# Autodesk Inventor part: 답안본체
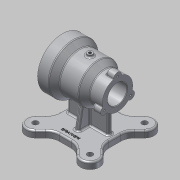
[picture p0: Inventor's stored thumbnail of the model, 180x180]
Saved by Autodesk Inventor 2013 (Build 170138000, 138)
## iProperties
Created: 2017-03
Part Number: 답안본체
Material: 알루미늄 6061
Document SubType Name: Modeling
Designer: Administrator
Density: 2.71 g/cm^3
Mass: 1007.36 g
Surface Area: 842.208 cm^2
Volume: 371.721 cm^3
Author: Administrator
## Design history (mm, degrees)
sketch "스케치2"
  geometry: L1 (0, 0)-(-100, 0); L2 (-100, 18.5)-(-100, 27.5); L3 (-100, 27.5)-(-77, 27.5); L4 (-77, 27.5)-(-65, 36); L5 (-65, 36)-(-31, 36); L6 (-31, 36)-(-20, 45); L7 (-20, 45)-(0, 45); L8 (0, 45)-(0, 36); L9 (-1, 35)-(-20, 35); L10 (-23, 32)-(-23, 29); L11 (-26, 26)-(-67, 26); L12 (-70, 23)-(-70, 20.5); L13 (-73, 17.5)-(-99, 17.5); L14 (-1, 35)-(0, 36); L15 (-99, 17.5)-(-100, 18.5); A1 r 3 centre (-20, 32) between (-20, 35) and (-23, 32); A2 r 3 centre (-26, 29) between (-26, 26) and (-23, 29); A3 r 3 centre (-67, 23) between (-67, 26) and (-70, 23); A4 r 3 centre (-73, 20.5) between (-73, 17.5) and (-70, 20.5); 6 further points
  constraints: 30 end point, 14 point on line, 8 point on circle, 8 tangent, 5 parallel, 5 perpendicular, 4 centre point, 3 equal radius, 1 horizontal
  dimensions: "d0" = 100 distance of L1.start L1.end; "d2" = 90 diameter of L7 L1; "d3" = 20 distance of L6.end L7.end; "d4" = 31 horizontal distance of L5.end L7.end; "d5" = 65 horizontal distance of L4.end L7.end; "d6" = 23 distance of L2.end L3.end; "d7" = 72 diameter of L5 L1; "d8" = 55 diameter of L3 L1; "d9" = 70 diameter of L9 L1; "d10" = 52 diameter of L11 L1; "d11" = 35 diameter of L13 L1; "d12" = 23 distance between parallel lines of L10 L8; "d13" = 47 distance of point (-23, 26) point (-70, 26); "d14" = 3 radius of A1; "d15" = 1 distance of L9.start point (0, 35); "d16" = 1 distance of L8.end point (0, 35) (= d15); "d17" = 1 distance of L13.end point (-100, 17.5) (= d15); "d18" = 1 distance of L2.start point (-100, 17.5) (= d17)
revolve "회전1" sketch "스케치2" stored, may be unused: angle "d19" = 90 deg
node "작업 평면3"
sketch "스케치4"
  geometry: L1 (100, 27.5)-(100, -27.5) reference; L2 (0, 0)-(100, 0); L3 (50, 0)-(50, -68.709); L4 (39.397, 45)-(60.603, 45); L5 (95, 10.603)-(95, -10.603); L6 (60.603, -45)-(39.397, -45); L7 (5, -10.603)-(5, 45); L8 (5, 45)-(95, -45); L9 (95, 45)-(5, -45); L10 (50, 0)-(0.503, 49.497); L11 (50, 0)-(99.497, 49.497); L12 (50, 0)-(0.503, -49.497); L13 (50, 0)-(99.497, -49.497); L14 (12.523, 61.518)-(21.719, 52.322); L15 (-11.518, 37.477)-(5, 20.958); L16 (-11.518, -37.477)-(-2.322, -28.281); L17 (12.523, -61.518)-(21.719, -52.322); L18 (87.477, -61.518)-(78.281, -52.322); L19 (111.518, -37.477)-(102.322, -28.281); L20 (87.477, 61.518)-(78.281, 52.322); L21 (111.518, 37.477)-(102.322, 28.281); A1 r 70 centre (50, 0) between (0.503, 49.497) and (99.497, 49.497); A2 r 17 centre (0.503, 49.497) between (12.523, 61.518) and (-11.518, 37.477); A3 r 17 centre (99.497, -49.497) between (87.477, -61.518) and (111.518, -37.477); A4 r 17 centre (0.503, -49.497) between (-11.518, -37.477) and (12.523, -61.518); A5 r 17 centre (99.497, 49.497) between (87.477, 61.518) and (111.518, 37.477); A6 r 25 centre (39.397, 70) between (21.719, 52.322) and (39.397, 45); A7 r 25 centre (60.603, 70) between (60.603, 45) and (78.281, 52.322); A8 r 25 centre (120, 10.603) between (102.322, 28.281) and (95, 10.603); A9 r 25 centre (120, -10.603) between (95, -10.603) and (102.322, -28.281); A10 r 25 centre (39.397, -70) between (39.397, -45) and (21.719, -52.322); A11 r 25 centre (-20, -10.603) between (-2.322, -28.281) and (5, -10.603); A12 r 25 centre (60.603, -70) between (78.281, -52.322) and (60.603, -45); 1 further point
  constraints: 40 end point, 26 point on circle, 22 tangent, 12 centre point, 12 point on line, 8 equal radius, 7 parallel, 6 midpoint, 5 coincident, 5 perpendicular, 1 collinear, 1 horizontal
  dimensions: "d38" = 140 diameter of A1; "d40" = 90 distance of L7.end L9.start; "d41" = 90 distance of L9.start L8.end; "d42" = 45 deg angle of L2 L10; "d43" = 90 deg angle of L11 L8; "d44" = 90 deg angle of L12 L13; "d45" = 34 diameter of A2; "d46" = 25 radius of A6; "d95" = 25 radius of A12
extrude "돌출2" join sketch "스케치4" distance "d47" = 12; taper "d48" = 0 deg
sketch "스케치5"
  geometry: L1 (39.397, -45)-(60.603, -45) reference; L2 (60.603, 45)-(39.397, 45) reference; L3 (50, 45)-(50, -45); L4 (50, 0)-(13, 0); L5 (13, 0)-(50, 0); L6 (87, 0)-(50, 0); L7 (87, 0)-(87, 4); L8 (87, 4)-(13, 4); L9 (13, 4)-(13, -4); L10 (13, -4)-(87, -4); L11 (87, -4)-(87, 0); 2 further points
  constraints: 18 end point, 4 collinear, 4 perpendicular, 3 midpoint, 2 parallel
  dimensions: "d52" = 4 distance between parallel lines of L8 L4; "d53" = 8 distance of L8.end L9.end; "d54" = 37 horizontal distance of L4.start L9.end; "d55" = 37 distance of L6.start L4.start
extrude "돌출3" join sketch "스케치5" stored distance "d56" = 12; taper "d57" = 0 deg
node "작업 평면4"
sketch "스케치6"
  geometry: L1 (-28.281, -70)-(-10.603, -70) reference; L2 (-28.281, -70)-(-37.477, -70) reference; L3 (-37.477, -70)-(-66.497, -70) reference; L4 (37.477, -70)-(20.958, -70) reference; L5 (66.497, -70)-(37.477, -70) reference; L6 (18.14, -31.096)-(25, -70); A1 r 36 centre (0, 0) between (4, -35.777) and (-4, -35.777) reference; 3 further points
  constraints: 2 end point, 1 point on circle, 1 point on line
  dimensions: "d62" = 100 deg angle of L5 L6; "d63" = 25 horizontal distance of L6.end point (0, 0)
feature "리브1" sketch "스케치6" dims "d64" = 1, "d65" = 8, "d66" = 0, "d67" = 0, "d68" = 1, "d69" = 1
sketch "스케치7"
  geometry: L1 (-28.281, -70)-(-10.603, -70) reference; L2 (-37.477, -70)-(-66.497, -70) reference; L3 (-28.281, -70)-(-37.477, -70) reference; L4 (-18.14, -31.096)-(-25, -70); A1 r 36 centre (0, 0) between (4, -35.777) and (-4, -35.777) reference; 2 further points
  constraints: 2 end point, 1 point on circle, 1 point on line
  dimensions: "d70" = 25 horizontal distance of point (0, 0) L4.end; "d71" = 100 deg angle of L2 L4
feature "리브2" sketch "스케치7" dims "d72" = 1, "d73" = 8, "d74" = 0, "d75" = 0, "d76" = 1, "d77" = 1
sketch "스케치8"
  geometry: L1 (-27.5, 0)-(0, 0); L2 (0, 0)-(13.75, -23.816); L3 (0, 0)-(13.75, 23.816); C1 r 20.5 at (0, 0) reference; C2 r 7 at (-27.5, 0); C3 r 26 at (0, 0) reference; A1 r 27.5 centre (0, 0) between (-27.5, 0) and (13.75, -23.816) reference
  constraints: 6 end point, 3 point on circle, 1 centre point, 1 horizontal, 1 horizontal alignment
  dimensions: "d78" = 14 diameter of C2; "d81" = 120 deg angle of L1 L2; "d83" = 120 deg angle of L1 L3
extrude "돌출4" join sketch "스케치8" distance "d85" = 15; taper "d86" = 0 deg
fillet "모깎기1" dims "d90" = 1
fillet "모깎기2" dims "d91" = 3
fillet "모깎기3" dims "d92" = 1
fillet "모깎기4" dims "d93" = 3
fillet "모깎기5" dims "d94" = 3
fillet "모깎기6" dims "d96" = 3
sketch "스케치9"
  geometry: L1 (-5, 35.651)-(-5, 40); L2 (-5, 40)-(5, 40); L3 (5, 35.651)-(5, 40); A1 r 36 centre (0, 0) between (4, -35.777) and (-4, -35.777) reference; A2 r 36 centre (0, 0) between (-4, -35.777) and (4, -35.777) reference; 1 further point
  constraints: 6 end point, 4 point on circle, 2 perpendicular, 1 parallel, 1 vertical
  dimensions: "d98" = 40 distance from line of L2 point (0, 0); "d99" = 10 distance of L1.end L2.end
extrude "돌출5" join sketch "스케치9" stored distance "d100" = 10; taper "d101" = 0 deg
fillet "모깎기8" dims "d102" = 5
fillet "모깎기9" dims "d103" = 3
sketch "스케치10"
  geometry: C1 r 5 at (0.503, 49.497); C2 r 5 at (99.497, 49.497); C3 r 5 at (99.497, -49.497); C4 r 5 at (0.503, -49.497); A1 r 14 centre (0.503, -49.497) between (-9.397, -39.598) and (10.402, -59.397) reference; A2 r 14 centre (99.497, -49.497) between (89.598, -59.397) and (109.397, -39.598) reference; A3 r 14 centre (99.497, 49.497) between (109.397, 39.598) and (89.598, 59.397) reference; A4 r 14 centre (0.503, 49.497) between (10.402, 59.397) and (-9.397, 39.598) reference; 1 further point
  constraints: 4 centre point, 4 coincident, 3 equal radius
  dimensions: "d104" = 10 diameter of C1
extrude "돌출6" cut sketch "스케치10" stored distance "d106" = 10; taper "d107" = 0 deg
fillet "모깎기10" dims "d108" = 3
fillet "모깎기11" dims "d109" = 3
sketch "스케치11"
  geometry: C1 r 5 at (0, 0) reference; C2 r 2.5 at (0, 0); 1 further point
  constraints: 1 centre point, 1 coincident
  dimensions: "d110" = 5 diameter of C2
extrude "돌출7" cut sketch "스케치11" stored distance "d112" = 10; taper "d113" = 0 deg
feature "스레드1" dims "d114" = 10, "d115" = 0
sketch "스케치12"
  geometry: C1 r 2 at (0, 0); A1 r 7 centre (0, 0) between (0.127, 6.999) and (0.127, -6.999) reference
  constraints: 1 centre point, 1 coincident
  dimensions: "d116" = 4 diameter of C1
hole "구멍1" sketch "스케치12" at (0, 0) diameter "d118" = 3.242; stored, may be unused: countersink angle "d122" = 90 deg, drill point angle "d124" = 118 deg; dims "d119" = 9, "d120" = 4, "d121" = 2, "d123" = 11
sketch "스케치13" dims "d128" = 80
  geometry: C1 r 36 at (0, 0) reference; C2 r 45 at (0, 0) reference; C3 r 2 at (40, 0); 1 further point
  constraints: 2 horizontal alignment, 1 centre point, 1 coincident, 2 other
  dimensions: "d131" = 4 diameter of C3
hole "구멍2" sketch "스케치13" at (40, 0) diameter "d132" = 3.242; stored, may be unused: countersink angle "d136" = 90 deg, drill point angle "d138" = 118 deg; dims "d133" = 9, "d134" = 4, "d135" = 2, "d137" = 11
sketch "스케치14"
  geometry: L1 (17.643, -32.598)-(82.357, -32.598); L2 (82.357, -32.598)-(82.357, -37.402); L3 (82.357, -37.402)-(17.643, -37.402); L4 (17.643, -37.402)-(17.643, -32.598); L5 (17.643, -35)-(82.357, -35); L6 (50, -32.598)-(50, -37.402); L7 (95, -10.603)-(95, 10.603) reference; 1 further point
  constraints: 4 end point, 4 midpoint, 2 other
  dimensions: "d142" = 35 distance from line of L5 point (0, 0); "d143" = 45 distance between parallel lines of L6 L7
extrude "돌출8" join sketch "스케치14" distance "d144" = 0.5; taper "d145" = 0 deg
node "솔리드1"
pattern_circular "원형 패턴1" dims angle "d88" = 360 deg
pattern_circular "원형 패턴2" dims angle "d126" = 360 deg
pattern_circular "원형 패턴3" dims angle "d140" = 360 deg
other parameters: "d35" = -82
